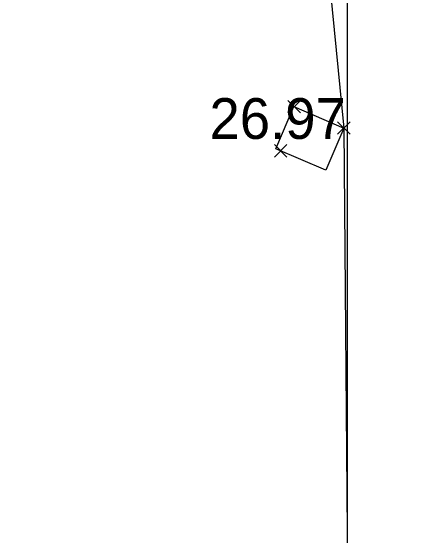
# Model space of a CAD drawing. Extents: x 37864 to 38032, y 453991 to 454052.
# Drawn here: x 37880.628 to 37883.488, y 454004.739 to 454008.409 of the extents above; entities that cross this region are included whole.
import ezdxf

# ---------------------------------------------------------------- set-up
doc = ezdxf.new("R2010")
doc.units = 0
for name, color, linetype in [('DH_CALCUL SURFACE-TEXTE', 7, 'Continuous'), ('GO_POTEAU', 7, 'Continuous'), ('PS_Bolt', 7, 'Continuous'), ('PS_Dim', 7, 'Continuous'), ('PS_Object', 7, 'Continuous'), ('PS_Weld', 7, 'Continuous'), ('SO_SANITAIRE DETAILLE', 7, 'Continuous')]:
    doc.layers.add(name, color=color, linetype=linetype)

# ---------------------------------------------------------------- blocks, each defined once
blk = doc.blocks.new('POTO_REC')
at = {"layer": 'PS_Weld'}
for p, q in [((0, 1), (1, 1)), ((0, 0), (0, 1)), ((1, 1), (1, 0)), ((1, 0), (0, 0))]:
    blk.add_line(p, q, dxfattribs=at)
blk = doc.blocks.new('POINT_DISPLAY')
for p, q in [((-0.04375, -0.04375), (0.04375, 0.04375)), ((-0.04375, 0.04375), (0.04375, -0.04375))]:
    blk.add_line(p, q)
blk = doc.blocks.new('POINTCOT')
blk.add_blockref('POINT_DISPLAY', (0, 0))

msp = doc.modelspace()

# ---------------------------------------------------------------- linework, layer by layer
at = {"layer": 'PS_Dim'}
msp.add_line((37882.9848, 454004.477), (37882.9848, 454030.3981), dxfattribs=at)
at = {"layer": 'PS_Object'}
msp.add_lwpolyline([(37895.242, 454005.2637), (37889.9429, 454005.1784), (37889.9169, 454004.7056), (37883.5913, 454004.4858), (37882.9848, 454004.477), (37882.9848, 454030.3981)], dxfattribs=at)
at = {"layer": 'SO_SANITAIRE DETAILLE'}
msp.add_line((37882.9848, 454004.477), (37882.9848, 454030.2847), dxfattribs=at)
msp.add_lwpolyline([(37877.7672, 454040.9193), (37880.278, 454037.4083), (37879.922, 454031.2706), (37881.6011, 454024.1531), (37881.6011, 454024.1531), (37881.6011, 454024.1531), (37881.675, 454023.8212), (37881.7814, 454022.2666), (37881.9007, 454020.7687), (37881.9266, 454020.3896), (37882.0081, 454019.1046), (37882.1138, 454018.1338), (37882.5612, 454015.4301), (37882.6563, 454013.5927), (37882.5766, 454012.1196), (37882.5924, 454010.9245), (37882.7852, 454009.3668), (37882.9596, 454007.5875), (37882.9848, 454004.477)], dxfattribs=at)

# ---------------------------------------------------------------- block references
at = {"layer": 'DH_CALCUL SURFACE-TEXTE', "rotation": 2.2526485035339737e-05}
for p in [(37882.6113, 454007.7365), (37882.9596, 454007.5875), (37882.5173, 454007.4275)]:
    msp.add_blockref('POINTCOT', p, dxfattribs=at)
at = {"layer": 'PS_Bolt', "xscale": 0.37999999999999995, "yscale": 0.32000000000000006, "rotation": 156.83421816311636}
msp.add_blockref('POTO_REC', (37882.9596, 454007.5875), dxfattribs=at)

# ---------------------------------------------------------------- texts
at = {"layer": 'GO_POTEAU'}
msp.add_text('26.97', height=0.285, rotation=0, dxfattribs=at).set_placement((37882.0194, 454007.5113))

doc.saveas('drawing.dxf')
